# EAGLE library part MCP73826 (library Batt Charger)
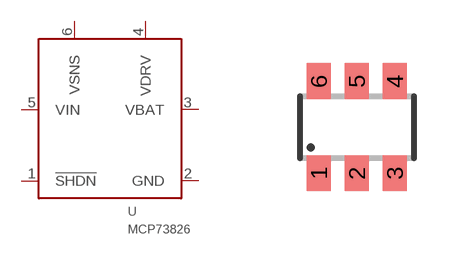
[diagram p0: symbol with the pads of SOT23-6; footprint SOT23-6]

Designator prefix U

## MCP73826  [SOT23-6]
1  !SHDN
2  GND
3  VBAT
4  VDRV
5  VIN
6  VSNS

## Footprint SOT23-6 (pad centres in mm)
SOT23 6pin
smd 0.6 x 0.9: 1 -0.95,-1.15; 2 0,-1.15; 3 0.95,-1.15; 4 0.95,1.15; 5 0,1.15; 6 -0.95,1.15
